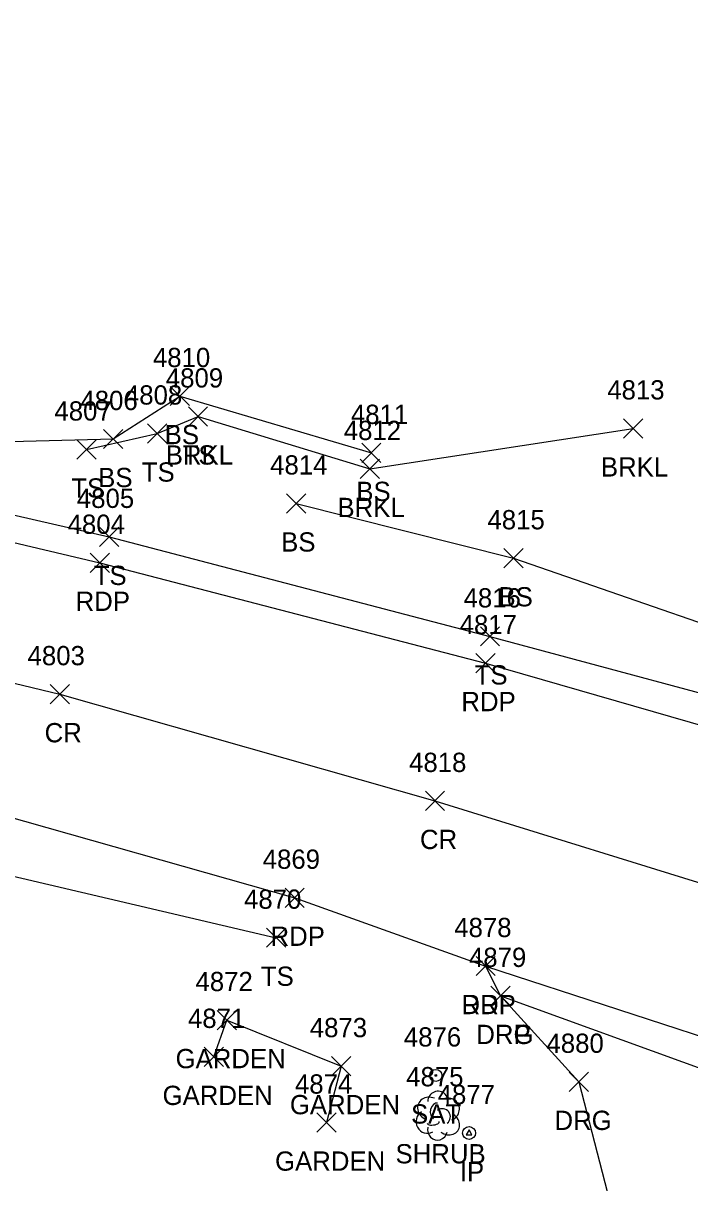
# Model space of a CAD drawing. Extents: x 1611797 to 1633212, y 298978 to 305475.
# Drawn here: x 1620200.5 to 1620269.8, y 301161.9 to 301282.2 of the extents above; entities that cross this region are included whole.
import ezdxf

# ---------------------------------------------------------------- set-up
doc = ezdxf.new("R2010")
doc.units = 0
for name, color, linetype in [('L_A', 7, 'Continuous'), ('L_I', 7, 'Continuous'), ('L_TIC', 7, 'Continuous'), ('LANT', 7, 'Continuous'), ('LAPB', 7, 'Continuous'), ('LAWE', 7, 'Continuous'), ('LELB', 7, 'Continuous'), ('LSH', 7, 'Continuous'), ('M_A', 7, 'Continuous'), ('M_I', 7, 'Continuous'), ('MPIR', 7, 'Continuous'), ('P_A', 7, 'Continuous'), ('P_I', 7, 'Continuous'), ('P_TIC', 7, 'Continuous'), ('PET', 7, 'Continuous'), ('PRC', 7, 'Continuous'), ('R_A', 7, 'Continuous'), ('R_I', 7, 'Continuous'), ('R_TIC', 7, 'Continuous'), ('RDG', 7, 'Continuous'), ('RDP', 7, 'Continuous')]:
    doc.layers.add(name, color=color, linetype=linetype)

msp = doc.modelspace()

# ---------------------------------------------------------------- linework, layer by layer
at = {"layer": 'L_TIC'}
for points in [[(1620215.8, 301242.54), (1620217.8, 301244.54)], [(1620217.8, 301242.54), (1620215.8, 301244.54)], [(1620217.7, 301240.42), (1620219.7, 301242.42)], [(1620219.7, 301240.42), (1620217.7, 301242.42)], [(1620217.7, 301240.42), (1620219.7, 301242.42)], [(1620219.7, 301240.42), (1620217.7, 301242.42)], [(1620213.45, 301238.65), (1620215.45, 301240.65)], [(1620215.45, 301238.65), (1620213.45, 301240.65)], [(1620262.9, 301239.18), (1620264.9, 301241.18)], [(1620264.9, 301239.18), (1620262.9, 301241.18)], [(1620208.89, 301238.08), (1620210.89, 301240.08)], [(1620210.89, 301238.08), (1620208.89, 301240.08)], [(1620206.13, 301236.99), (1620208.13, 301238.99)], [(1620208.13, 301236.99), (1620206.13, 301238.99)], [(1620235.7, 301236.64), (1620237.7, 301238.64)], [(1620237.7, 301236.64), (1620235.7, 301238.64)], [(1620235.53, 301234.97), (1620237.53, 301236.97)], [(1620237.53, 301234.97), (1620235.53, 301236.97)], [(1620227.89, 301231.39), (1620229.89, 301233.39)], [(1620229.89, 301231.39), (1620227.89, 301233.39)], [(1620208.46, 301227.92), (1620210.46, 301229.92)], [(1620210.46, 301227.92), (1620208.46, 301229.92)], [(1620250.46, 301225.7), (1620252.46, 301227.7)], [(1620252.46, 301225.7), (1620250.46, 301227.7)], [(1620248.02, 301217.59), (1620250.02, 301219.59)], [(1620250.02, 301217.59), (1620248.02, 301219.59)], [(1620225.82, 301186.31), (1620227.82, 301188.31)], [(1620227.82, 301186.31), (1620225.82, 301188.31)], [(1620220.7, 301177.76), (1620222.7, 301179.76)], [(1620222.7, 301177.76), (1620220.7, 301179.76)], [(1620219.35, 301173.94), (1620221.35, 301175.94)], [(1620221.35, 301173.94), (1620219.35, 301175.94)], [(1620232.57, 301172.98), (1620234.57, 301174.98)], [(1620234.57, 301172.98), (1620232.57, 301174.98)], [(1620231.03, 301167.12), (1620233.03, 301169.12)], [(1620233.03, 301167.12), (1620231.03, 301169.12)]]:
    msp.add_lwpolyline(points, dxfattribs=at)
at = {"layer": 'LANT'}
for radius in [0.625, 0.0833]:
    msp.add_circle((1620243.4, 301173.01), radius, dxfattribs=at)
at = {"layer": 'LAPB'}
msp.add_lwpolyline([(1620220.35, 301174.94), (1620221.7, 301178.76), (1620233.57, 301173.98), (1620232.03, 301168.12)], dxfattribs=at)
at = {"layer": 'LAWE'}
msp.add_lwpolyline([(1620218.7, 301241.42), (1620236.53, 301235.97), (1620263.9, 301240.18)], dxfattribs=at)
at = {"layer": 'LELB'}
for points in [[(1619717.05, 301402.62), (1619729.49, 301382.85), (1619751.83, 301362.42), (1619788.58, 301341.51), (1619840.33, 301321.37), (1619859.82, 301312.4), (1619885.93, 301308.98), (1619917.76, 301301.6), (1619954.63, 301284.39), (1619995.46, 301278.81), (1620037.59, 301270.1), (1620080.58, 301262.9), (1620111.05, 301256.31), (1620134.36, 301250.9), (1620155.92, 301243.69), (1620184.2, 301240.01), (1620186.37, 301239.29), (1620187.23, 301238.52), (1620209.89, 301239.08), (1620216.8, 301243.54), (1620236.7, 301237.64)], [(1619712.43, 301401.44), (1619713.12, 301390.21), (1619725.41, 301373.61), (1619737.56, 301363.75), (1619786.34, 301337.07), (1619800.28, 301327.59), (1619837.75, 301316), (1619857.62, 301306.82), (1619872.16, 301301.99), (1619887.37, 301302.9), (1619915.15, 301296.19), (1619953.85, 301281.7), (1619995.44, 301273.48), (1620035.7, 301263.81), (1620079.78, 301255.69), (1620110.34, 301250.13), (1620133.61, 301245.85), (1620185.9, 301234.31), (1620209.46, 301228.92), (1620249.02, 301218.59), (1620282.74, 301209.51), (1620314.25, 301201.24), (1620350.31, 301189.61), (1620412.81, 301166.44)], [(1620207.13, 301237.99), (1620214.45, 301239.65), (1620218.7, 301241.42)], [(1620228.89, 301232.39), (1620251.46, 301226.7), (1620285.09, 301215.07), (1620316.24, 301206.99), (1620354.54, 301198.89), (1620379.67, 301192.77)], [(1620190.54, 301187.24), (1620197.55, 301194.14), (1620226.82, 301187.31)]]:
    msp.add_lwpolyline(points, dxfattribs=at)
at = {"layer": 'LSH'}
msp.add_line((1620243.58, 301168.88), (1620243.58, 301168.88), dxfattribs=at)
msp.add_line((1620243.58, 301168.88), (1620243.58, 301168.88), dxfattribs=at)
msp.add_arc((1620243.62, 301170.32), 1.05, 335.5272, 180.9563, dxfattribs=at)
for centre, major_axis, ratio, start_param, end_param in [((1620242.79, 301169.55), (1.21, -0.51), 0.895232, 1.570796, 4.712389), ((1620244.62, 301169.47), (-1.14, -0.48), 0.949671, 1.570796, 4.712389), ((1620242.49, 301168.18), (0.58, -1.04), 0.959034, 3.141593, 6.283185), ((1620243.37, 301169.34), (-0.208, -0.792), 0.645439, 3.141593, 6.283185), ((1620244.08, 301168.72), (-0.5, 0.667), 0.989748, 3.141593, 6.283185), ((1620243.12, 301168.13), (-0.625, -0.083), 0.423636, 0, 3.141593), ((1620244.58, 301168.05), (-1.09, 0.79), 0.841452, 1.570796, 4.712389), ((1620243.58, 301167.38), (0.26, 1.06), 0.942809, 1.570796, 4.712389)]:
    msp.add_ellipse(centre, major_axis=major_axis, ratio=ratio, start_param=start_param, end_param=end_param, dxfattribs=at)
at = {"layer": 'MPIR'}
msp.add_lwpolyline([(1620246.85, 301167.36), (1620246.56, 301166.86), (1620247.14, 301166.86)], close=True, dxfattribs=at)
msp.add_circle((1620246.85, 301167.03), 0.667, dxfattribs=at)
at = {"layer": 'P_TIC'}
for points in [[(1620207.5, 301225.23), (1620209.5, 301227.23)], [(1620209.5, 301225.23), (1620207.5, 301227.23)], [(1620247.56, 301214.82), (1620249.56, 301216.82)], [(1620249.56, 301214.82), (1620247.56, 301216.82)], [(1620203.34, 301211.59), (1620205.34, 301213.59)], [(1620205.34, 301211.59), (1620203.34, 301213.59)], [(1620242.31, 301200.51), (1620244.31, 301202.51)], [(1620244.31, 301200.51), (1620242.31, 301202.51)], [(1620227.74, 301190.46), (1620229.74, 301192.46)], [(1620229.74, 301190.46), (1620227.74, 301192.46)], [(1620247.57, 301183.37), (1620249.57, 301185.37)], [(1620249.57, 301183.37), (1620247.57, 301185.37)]]:
    msp.add_lwpolyline(points, dxfattribs=at)
at = {"layer": 'PET'}
for points in [[(1619950.83, 301272.88), (1619994.49, 301265.52), (1620034.74, 301259.86), (1620079.84, 301252.7), (1620110.29, 301247.77), (1620134.1, 301243.25), (1620157.04, 301238.24), (1620185.22, 301231.73), (1620208.5, 301226.23), (1620248.56, 301215.82), (1620281.32, 301206.35), (1620312.57, 301196.92), (1620349.07, 301184.5), (1620413.64, 301162.8), (1620434.83, 301155.43), (1620462.97, 301144.02), (1620503.17, 301127.44), (1620525.17, 301116.54), (1620575.61, 301095.66), (1620609.9, 301081.02), (1620652.81, 301063.66), (1620688.75, 301050.82)], [(1619949.02, 301246.88), (1619987.97, 301240.43), (1620023.99, 301234.8), (1620066.3, 301227.5), (1620107.62, 301220.15), (1620151.12, 301211.95), (1620161.97, 301208.85), (1620163.52, 301206.06), (1620192.25, 301199.71), (1620196.02, 301200.72), (1620228.74, 301191.46), (1620248.57, 301184.37), (1620276.18, 301175.36)]]:
    msp.add_lwpolyline(points, dxfattribs=at)
at = {"layer": 'PRC'}
msp.add_lwpolyline([(1619950.93, 301259.45), (1619990.95, 301252.78), (1620025.87, 301247.29), (1620068.06, 301240.98), (1620110.75, 301233.41), (1620153.16, 301224.91), (1620204.34, 301212.59), (1620243.31, 301201.51), (1620275.93, 301191.41), (1620310.63, 301179.99), (1620341.66, 301169.03), (1620406.06, 301144.45), (1620426.68, 301136.25), (1620459.58, 301122.78), (1620495.22, 301107.64), (1620519.86, 301097.12), (1620567.45, 301077.15), (1620602.44, 301063.05), (1620645.54, 301046.08), (1620683.56, 301031.25)], dxfattribs=at)
at = {"layer": 'R_TIC'}
for points in [[(1620247.57, 301183.37), (1620249.57, 301185.37)], [(1620249.57, 301183.37), (1620247.57, 301185.37)], [(1620249.11, 301180.27), (1620251.11, 301182.27)], [(1620251.11, 301180.27), (1620249.11, 301182.27)], [(1620249.11, 301180.27), (1620251.11, 301182.27)], [(1620251.11, 301180.27), (1620249.11, 301182.27)], [(1620257.24, 301171.35), (1620259.24, 301173.35)], [(1620259.24, 301171.35), (1620257.24, 301173.35)]]:
    msp.add_lwpolyline(points, dxfattribs=at)
at = {"layer": 'RDG'}
msp.add_lwpolyline([(1620250.11, 301181.27), (1620258.24, 301172.35), (1620262.3, 301156.67)], dxfattribs=at)
at = {"layer": 'RDP'}
msp.add_lwpolyline([(1620248.57, 301184.37), (1620250.11, 301181.27), (1620275.3, 301172.14), (1620294.93, 301165.46), (1620300.31, 301166.68)], dxfattribs=at)

# ---------------------------------------------------------------- texts
at = {"layer": 'L_A'}
for s, p in [('BS', (1620215.24, 301238.54)), ('BRKL', (1620215.35, 301236.42)), ('TS', (1620217.11, 301236.42)), ('TS', (1620212.86, 301234.65)), ('BRKL', (1620260.54, 301235.18)), ('BS', (1620208.33, 301234.08)), ('TS', (1620205.54, 301232.99)), ('BS', (1620235.14, 301232.64)), ('BRKL', (1620233.18, 301230.97)), ('BS', (1620227.33, 301227.39)), ('TS', (1620207.87, 301223.92)), ('BS', (1620249.9, 301221.7)), ('TS', (1620247.43, 301213.59)), ('TS', (1620225.23, 301182.31)), ('GARDEN', (1620216.37, 301173.76)), ('GARDEN', (1620215.02, 301169.94)), ('GARDEN', (1620228.24, 301168.98)), ('SAT', (1620240.82, 301168.01)), ('SHRUB', (1620239.21, 301163.88)), ('GARDEN', (1620226.7, 301163.12))]:
    msp.add_text(s, height=2, dxfattribs=at).set_placement(p)
at = {"layer": 'L_I'}
for s, p in [('4810', (1620214.02, 301246.54)), ('4809', (1620215.36, 301244.42)), ('4809', (1620215.36, 301244.42)), ('4813', (1620261.2, 301243.18)), ('4806', (1620206.49, 301242.08)), ('4808', (1620211.11, 301242.65)), ('4807', (1620203.79, 301240.99)), ('4811', (1620234.58, 301240.64)), ('4812', (1620233.84, 301238.97)), ('4814', (1620226.19, 301235.39)), ('4805', (1620206.12, 301231.92)), ('4815', (1620248.76, 301229.7)), ('4816', (1620246.28, 301221.59)), ('4870', (1620223.48, 301190.31)), ('4872', (1620218.44, 301181.76)), ('4871', (1620217.66, 301177.94)), ('4873', (1620230.31, 301176.98)), ('4876', (1620240.08, 301176.01)), ('4874', (1620228.77, 301171.12)), ('4875', (1620240.32, 301171.88))]:
    msp.add_text(s, height=2, dxfattribs=at).set_placement(p)
at = {"layer": 'M_A'}
msp.add_text('IP', height=2, dxfattribs=at).set_placement((1620245.89, 301162.03))
at = {"layer": 'M_I'}
msp.add_text('4877', height=2, dxfattribs=at).set_placement((1620243.59, 301170.03))
at = {"layer": 'P_A'}
for s, p in [('RDP', (1620205.99, 301221.23)), ('RDP', (1620246.05, 301210.82)), ('CR', (1620202.77, 301207.59)), ('CR', (1620241.75, 301196.51)), ('RDP', (1620226.23, 301186.46)), ('RDP', (1620246.06, 301179.37))]:
    msp.add_text(s, height=2, dxfattribs=at).set_placement(p)
at = {"layer": 'P_I'}
for s, p in [('4804', (1620205.16, 301229.23)), ('4817', (1620245.87, 301218.82)), ('4803', (1620201, 301215.59)), ('4818', (1620240.62, 301204.51)), ('4869', (1620225.42, 301194.46)), ('4878', (1620245.31, 301187.37))]:
    msp.add_text(s, height=2, dxfattribs=at).set_placement(p)
at = {"layer": 'R_A'}
for s, p in [('DRP', (1620246.06, 301179.37)), ('DRG', (1620247.6, 301176.27)), ('DRP', (1620247.6, 301176.27)), ('DRG', (1620255.72, 301167.35))]:
    msp.add_text(s, height=2, dxfattribs=at).set_placement(p)
at = {"layer": 'R_I'}
for s, p in [('4878', (1620245.31, 301187.37)), ('4879', (1620246.84, 301184.27)), ('4879', (1620246.84, 301184.27)), ('4880', (1620254.89, 301175.35))]:
    msp.add_text(s, height=2, dxfattribs=at).set_placement(p)

doc.saveas('drawing.dxf')
